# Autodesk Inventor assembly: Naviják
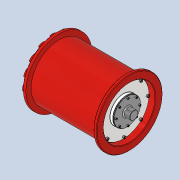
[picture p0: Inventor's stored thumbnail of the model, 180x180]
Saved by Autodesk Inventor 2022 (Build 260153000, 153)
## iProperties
Created: 2025-05
Part Number: Naviják
Document SubType Name: Assembly
Designer: jbart
Author: jbart
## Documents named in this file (37)
- C:\Users\jbart\OneDrive\Dokumenty\Inventor\Převodovka navijáku\Naviják.iam
- C:\Users\jbart\OneDrive\Dokumenty\Inventor\Převodovka navijáku\Bočnice.ipt
- C:\Users\jbart\OneDrive\Dokumenty\Inventor\Převodovka navijáku\Pouzdro.ipt
- C:\Users\jbart\OneDrive\Dokumenty\Inventor\Content Center Files\R2022\cs-CZ\CSN 02 4630\CSN 02 4630 - 6414.ipt
- C:\Users\jbart\OneDrive\Dokumenty\Inventor\Content Center Files\R2022\cs-CZ\CSN 02 2931\CSN 02 2931 - 180.ipt
- C:\Users\jbart\OneDrive\Dokumenty\Inventor\Content Center Files\R2022\cs-CZ\CSN 02 2930\CSN 02 2930 - 70.ipt
- C:\Users\jbart\OneDrive\Dokumenty\Inventor\Převodovka navijáku\Hřídel I.ipt
- C:\Users\jbart\OneDrive\Dokumenty\Inventor\Content Center Files\R2022\cs-CZ\CSN 02 2562  A\CSN 02 2562 - 16x10x50.ipt
- C:\Users\jbart\OneDrive\Dokumenty\Inventor\Převodovka navijáku\Hřídel II.iam
- C:\Users\jbart\OneDrive\Dokumenty\Inventor\Content Center Files\R2022\cs-CZ\CSN 02 2930\CSN 02 2930 - 40.ipt
- C:\Users\jbart\OneDrive\Dokumenty\Inventor\Content Center Files\R2022\cs-CZ\CSN 02 4630\CSN 02 4630 - 6208.ipt
- C:\Users\jbart\OneDrive\Dokumenty\Inventor\Content Center Files\R2022\cs-CZ\CSN 02 4720\CSN  02 4720 - 32948.ipt
- C:\Users\jbart\OneDrive\Dokumenty\Inventor\Content Center Files\R2022\cs-CZ\CSN 02 4720\CSN  02 4720 - 32952.ipt
- C:\Users\jbart\OneDrive\Dokumenty\Inventor\Převodovka navijáku\Unášeč B-2.ipt
- C:\Users\jbart\OneDrive\Dokumenty\Inventor\Převodovka navijáku\Korunové kolo 1.iam
- C:\Users\jbart\OneDrive\Dokumenty\Inventor\Převodovka navijáku\Satelit B.iam
- C:\Users\jbart\OneDrive\Dokumenty\Inventor\Převodovka navijáku\Hřídel V.ipt
- C:\Users\jbart\OneDrive\Dokumenty\Inventor\Content Center Files\R2022\cs-CZ\CSN 02 4630\CSN 02 4630 - 6010.ipt
- C:\Users\jbart\OneDrive\Dokumenty\Inventor\Převodovka navijáku\Distanční kroužek.ipt
- C:\Users\jbart\OneDrive\Dokumenty\Inventor\Content Center Files\R2022\cs-CZ\CSN 02 2930\CSN 02 2930 - 50.ipt
- C:\Users\jbart\OneDrive\Dokumenty\Inventor\Převodovka navijáku\Unášeč B-1.ipt
- C:\Users\jbart\OneDrive\Dokumenty\Inventor\Převodovka navijáku\Unášeč A-2.ipt
- C:\Users\jbart\OneDrive\Dokumenty\Inventor\Převodovka navijáku\Hřídel III.iam
- C:\Users\jbart\OneDrive\Dokumenty\Inventor\Převodovka navijáku\Hřídel IV.ipt
- C:\Users\jbart\OneDrive\Dokumenty\Inventor\Převodovka navijáku\Satelit A.iam
- C:\Users\jbart\OneDrive\Dokumenty\Inventor\Převodovka navijáku\Unášeč A-1.ipt
- C:\Users\jbart\OneDrive\Dokumenty\Inventor\Převodovka navijáku\Korunové kolo 2.iam
- C:\Users\jbart\OneDrive\Dokumenty\Inventor\Převodovka navijáku\Pouzdro II.ipt
- C:\Users\jbart\OneDrive\Dokumenty\Inventor\Content Center Files\R2022\cs-CZ\CSN 02 1143  A\CSN 02 1143 - M12 x 1,75 x 25(1).ipt
- C:\Users\jbart\OneDrive\Dokumenty\Inventor\Převodovka navijáku\Víčko.ipt
- C:\Users\jbart\OneDrive\Dokumenty\Inventor\Content Center Files\R2022\cs-CZ\CSN 02 1143  A\CSN 02 1143 - M12 x 1,75 x 20(1).ipt
- C:\Users\jbart\OneDrive\Dokumenty\Inventor\Převodovka navijáku\Víčko II.ipt
- C:\Users\jbart\OneDrive\Dokumenty\Inventor\Převodovka navijáku\Výstup.ipt
- C:\Users\jbart\OneDrive\Dokumenty\Inventor\Content Center Files\R2022\cs-CZ\CSN 02 1143  A\CSN 02 1143 - M12 x 1,75 x 22(1).ipt
- C:\Users\jbart\OneDrive\Dokumenty\Inventor\Převodovka navijáku\Buben.ipt
- C:\Users\jbart\OneDrive\Dokumenty\Inventor\Content Center Files\R2022\cs-CZ\CSN 02 1143  A\CSN 02 1143 - M16 x 2 x 45(1).ipt
- C:\Users\jbart\OneDrive\Dokumenty\Inventor\Převodovka navijáku\Distanční kroužek II.ipt
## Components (112 placed, 36 different names)
1. Bočnice:1 — Stejný směr:1, Proti sobě:1, Proti sobě:2, Proti sobě:5, Proti sobě:6, Stejný směr:2, Stejný směr:3, Proti sobě:23, Proti sobě:24, Proti sobě:25, Stejný směr:4, Proti sobě:27, Proti sobě:28, Proti sobě:29, Proti sobě:30, Proti sobě:31, Proti sobě:32, Proti sobě:35, Proti sobě:145, Proti sobě:146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
2. Pouzdro:1 — Proti sobě:7, Proti sobě:8, Proti sobě:9, Proti sobě:10, Proti sobě:14, Proti sobě:15, Proti sobě:16, Proti sobě:17, Proti sobě:18
3. CSN 02 4630 6414:1 — Proti sobě:143, Proti sobě:144
4. CSN 02 4630 6414:2 — Proti sobě:7, Proti sobě:10, Proti sobě:27, Proti sobě:28
5. CSN 02 2931 180:1 — Proti sobě:5, Proti sobě:6, Stejný směr:2
6. CSN 02 2930 70:1 — Proti sobě:8, Proti sobě:9, Stejný směr:3
7. Hřídel I:1 — Proti sobě:11, Proti sobě:12, Proti sobě:13, Proti sobě:14, Proti sobě:150
8. CSN 02 2562 A 16x10x50:1 — Proti sobě:11, Proti sobě:12, Proti sobě:13, Proti sobě:15
9. Hřídel II:1 [sub-assembly] — Proti sobě:16, Proti sobě:17, Proti sobě:18, Proti sobě:19, Proti sobě:20, Proti sobě:21, Proti sobě:22, Proti sobě:26, Proti sobě:34, Proti sobě:52, Rotace:4, Rotace:5, Rotace:6, Rotace:7, Proti sobě:138, Proti sobě:167
10. CSN 02 2930 40:1 — Proti sobě:21, Proti sobě:22
11. CSN 02 4630 6208:1 — Proti sobě:19, Proti sobě:20, Proti sobě:151, Proti sobě:152
12. CSN 02 4720 32948:1 — Proti sobě:23, Proti sobě:24, Proti sobě:142
13. CSN 02 4720 32952:1 — Proti sobě:25, Stejný směr:4, Stejný směr:10
14. Unášeč B-2:1 — Proti sobě:26, Proti sobě:29, Proti sobě:30, Proti sobě:31, Proti sobě:33, Proti sobě:49, Proti sobě:50, Proti sobě:51, Proti sobě:68, Proti sobě:69, Proti sobě:70, Proti sobě:84, Proti sobě:85, Proti sobě:86
15. Korunové kolo 1:1 [sub-assembly] — Proti sobě:34, Proti sobě:35, Stejný směr:8, Proti sobě:141
16. Satelit B:1 [sub-assembly] — Proti sobě:36, Proti sobě:37, Proti sobě:38, Proti sobě:39, Rotace:1, Stejný směr:7
17. Hřídel V:1 — Proti sobě:40, Proti sobě:41, Proti sobě:43, Proti sobě:45, Proti sobě:46, Proti sobě:47, Proti sobě:48, Proti sobě:49, Proti sobě:53
18. CSN 02 4630 6010:1 — Proti sobě:36, Proti sobě:37, Proti sobě:40, Proti sobě:42
19. CSN 02 4630 6010:2 — Proti sobě:38, Proti sobě:39, Proti sobě:44
20. Distanční kroužek:1 — Proti sobě:41, Proti sobě:42, Proti sobě:51
21. Distanční kroužek:2 — Proti sobě:43, Proti sobě:44, Proti sobě:54
22. CSN 02 2930 50:1 — Proti sobě:45, Proti sobě:48, Proti sobě:50
23. CSN 02 2930 50:2 — Proti sobě:46, Proti sobě:47
24. Unášeč B-1:1 — Proti sobě:52, Proti sobě:53, Proti sobě:54, Proti sobě:87
25. Satelit B:2 [sub-assembly] — Rotace:3, Stejný směr:9
26. Hřídel V:2 — Proti sobě:68
27. CSN 02 4630 6010:3
28. CSN 02 4630 6010:4
29. Distanční kroužek:3 — Proti sobě:70
30. Distanční kroužek:4
31. CSN 02 2930 50:3 — Proti sobě:69
32. CSN 02 2930 50:4
33. Satelit B:3 [sub-assembly] — Rotace:2
34. Hřídel V:3 — Proti sobě:84
35. CSN 02 4630 6010:5
36. CSN 02 4630 6010:6
37. Distanční kroužek:5 — Proti sobě:86
38. Distanční kroužek:6
39. CSN 02 2930 50:5 — Proti sobě:85
40. CSN 02 2930 50:6
41. Unášeč A-2:1 — Proti sobě:87, Proti sobě:88, Proti sobě:89, Stejný směr:6, Proti sobě:103, Proti sobě:104, Proti sobě:105, Proti sobě:132, Proti sobě:133, Proti sobě:134, Proti sobě:135, Proti sobě:136, Proti sobě:137, Rotace:7
42. Hřídel III:1 [sub-assembly] — Proti sobě:88, Proti sobě:89, Stejný směr:6, Rotace:1, Rotace:2, Rotace:3, Stejný směr:7, Rotace:8, Proti sobě:168
43. Hřídel IV:1 — Proti sobě:94, Proti sobě:95, Proti sobě:97, Proti sobě:99, Proti sobě:100, Proti sobě:101, Proti sobě:102, Proti sobě:103, Proti sobě:139
44. Distanční kroužek:7 — Proti sobě:95, Proti sobě:96, Proti sobě:105
45. Distanční kroužek:8 — Proti sobě:97, Proti sobě:98, Proti sobě:140
46. CSN 02 2930 50:7 — Proti sobě:101, Proti sobě:102
47. CSN 02 2930 50:8 — Proti sobě:99, Proti sobě:100, Proti sobě:104
48. Satelit A:1 [sub-assembly] — Proti sobě:90, Proti sobě:91, Proti sobě:92, Proti sobě:93, Rotace:5, Stejný směr:8
49. CSN 02 4630 6010:7 — Proti sobě:90, Proti sobě:91, Proti sobě:94, Proti sobě:96
50. CSN 02 4630 6010:8 — Proti sobě:92, Proti sobě:93, Proti sobě:98
51. Hřídel IV:2 — Proti sobě:135
52. Distanční kroužek:9 — Proti sobě:137
53. Distanční kroužek:10
54. CSN 02 2930 50:9
55. CSN 02 2930 50:10 — Proti sobě:136
56. Satelit A:2 [sub-assembly] — Rotace:4
57. CSN 02 4630 6010:9
58. CSN 02 4630 6010:10
59. Hřídel IV:3 — Proti sobě:132
60. Distanční kroužek:11 — Proti sobě:134
61. Distanční kroužek:12
62. CSN 02 2930 50:11
63. CSN 02 2930 50:12 — Proti sobě:133
64. Satelit A:3 [sub-assembly] — Rotace:6
65. CSN 02 4630 6010:11
66. CSN 02 4630 6010:12
67. Unášeč A-1:1 — Proti sobě:138, Proti sobě:139, Proti sobě:140
68. Korunové kolo 2:1 [sub-assembly] — Proti sobě:141, Stejný směr:9, Rotace:8, Proti sobě:158, Proti sobě:159
69. Pouzdro II:1 — Proti sobě:142, Stejný směr:10, Proti sobě:160, Proti sobě:161, Proti sobě:163, Stejný směr:11
70. Víčko:1 — Proti sobě:143, Proti sobě:144, Proti sobě:145, Proti sobě:146, Proti sobě:147, Proti sobě:149, Proti sobě:150
71. Víčko II:1 — Proti sobě:151, Proti sobě:152, Proti sobě:153, Proti sobě:154, Proti sobě:155, Proti sobě:164, Proti sobě:165, Proti sobě:166
72. Výstup:1 — Proti sobě:153, Proti sobě:154, Proti sobě:155, Proti sobě:156, Proti sobě:157
73. Buben:1 — Proti sobě:158, Proti sobě:159, Proti sobě:160, Proti sobě:164
74. Distanční kroužek II:1 — Proti sobě:167, Proti sobě:168
75. CSN 02 1143 A M12 x 25:1 — Proti sobě:32, Proti sobě:33
76. CSN 02 1143 A M12 x 25:2
77. CSN 02 1143 A M12 x 25:3
78. CSN 02 1143 A M12 x 25:4
79. CSN 02 1143 A M12 x 25:5
80. CSN 02 1143 A M12 x 25:6
81. CSN 02 1143 A M12 x 20:1 — Proti sobě:148, Proti sobě:149
82. CSN 02 1143 A M12 x 20:2
83. CSN 02 1143 A M12 x 20:3
84. CSN 02 1143 A M12 x 20:4
85. CSN 02 1143 A M12 x 20:5
86. CSN 02 1143 A M12 x 20:6
87. CSN 02 1143 A M12 x 20:7
88. CSN 02 1143 A M12 x 20:8
89. CSN 02 1143 A M12 x 22:1 — Proti sobě:156, Proti sobě:157
90. CSN 02 1143 A M12 x 22:2
91. CSN 02 1143 A M12 x 22:3
92. CSN 02 1143 A M12 x 22:4
93. CSN 02 1143 A M12 x 22:5
94. CSN 02 1143 A M12 x 22:6
95. CSN 02 1143 A M12 x 22:7
96. CSN 02 1143 A M12 x 22:8
97. CSN 02 1143 A M16 x 45:1 — Proti sobě:161, Proti sobě:163
98. CSN 02 1143 A M16 x 45:3
99. CSN 02 1143 A M16 x 45:4
100. CSN 02 1143 A M16 x 45:5
101. CSN 02 1143 A M16 x 45:6
102. CSN 02 1143 A M16 x 45:7
103. CSN 02 1143 A M16 x 45:8
104. CSN 02 1143 A M16 x 45:9
105. CSN 02 1143 A M16 x 45:2 — Proti sobě:165, Proti sobě:166
106. CSN 02 1143 A M16 x 45:10
107. CSN 02 1143 A M16 x 45:11
108. CSN 02 1143 A M16 x 45:12
109. CSN 02 1143 A M16 x 45:13
110. CSN 02 1143 A M16 x 45:14
111. CSN 02 1143 A M16 x 45:15
112. CSN 02 1143 A M16 x 45:16
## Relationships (131: Mate 113, Flush 10, RelateRotation 8)
- Stejný směr:1 [Flush]: Bočnice:1
- Proti sobě:1 [Mate]: Bočnice:1
- Proti sobě:2 [Mate]: Bočnice:1
- Proti sobě:5 [Mate]: Bočnice:1 ↔ CSN 02 2931 180:1
- Proti sobě:6 [Mate]: Bočnice:1 ↔ CSN 02 2931 180:1
- Stejný směr:2 [Flush]: Bočnice:1 ↔ CSN 02 2931 180:1
- Proti sobě:7 [Mate]: Pouzdro:1 ↔ CSN 02 4630 6414:2
- Proti sobě:8 [Mate]: Pouzdro:1 ↔ CSN 02 2930 70:1
- Proti sobě:9 [Mate]: Pouzdro:1 ↔ CSN 02 2930 70:1
- Stejný směr:3 [Flush]: Bočnice:1 ↔ CSN 02 2930 70:1
- Proti sobě:10 [Mate]: Pouzdro:1 ↔ CSN 02 4630 6414:2
- Proti sobě:11 [Mate]: Hřídel I:1 ↔ CSN 02 2562 A 16x10x50:1
- Proti sobě:12 [Mate]: Hřídel I:1 ↔ CSN 02 2562 A 16x10x50:1
- Proti sobě:13 [Mate]: Hřídel I:1 ↔ CSN 02 2562 A 16x10x50:1
- Proti sobě:14 [Mate]: Pouzdro:1 ↔ Hřídel I:1
- Proti sobě:15 [Mate]: Pouzdro:1 ↔ CSN 02 2562 A 16x10x50:1
- Proti sobě:16 [Mate]: Pouzdro:1 ↔ Hřídel II:1
- Proti sobě:17 [Mate]: Pouzdro:1 ↔ Hřídel II:1
- Proti sobě:18 [Mate]: Pouzdro:1 ↔ Hřídel II:1
- Proti sobě:19 [Mate]: Hřídel II:1 ↔ CSN 02 4630 6208:1
- Proti sobě:20 [Mate]: Hřídel II:1 ↔ CSN 02 4630 6208:1
- Proti sobě:21 [Mate]: Hřídel II:1 ↔ CSN 02 2930 40:1
- Proti sobě:22 [Mate]: Hřídel II:1 ↔ CSN 02 2930 40:1
- Proti sobě:23 [Mate]: Bočnice:1 ↔ CSN 02 4720 32948:1
- Proti sobě:24 [Mate]: Bočnice:1 ↔ CSN 02 4720 32948:1
- Proti sobě:25 [Mate]: Bočnice:1 ↔ CSN 02 4720 32952:1
- Stejný směr:4 [Flush]: Bočnice:1 ↔ CSN 02 4720 32952:1
- Proti sobě:26 [Mate]: Hřídel II:1 ↔ Unášeč B-2:1
- Proti sobě:27 [Mate]: Bočnice:1 ↔ CSN 02 4630 6414:2
- Proti sobě:28 [Mate]: Bočnice:1 ↔ CSN 02 4630 6414:2
- Proti sobě:29 [Mate]: Bočnice:1 ↔ Unášeč B-2:1
- Proti sobě:30 [Mate]: Bočnice:1 ↔ Unášeč B-2:1
- Proti sobě:31 [Mate]: Bočnice:1 ↔ Unášeč B-2:1
- Proti sobě:32 [Mate]: Bočnice:1 ↔ CSN 02 1143 A M12 x 25:1
- Proti sobě:33 [Mate]: Unášeč B-2:1 ↔ CSN 02 1143 A M12 x 25:1
- Proti sobě:34 [Mate]: Hřídel II:1 ↔ Korunové kolo 1:1
- Proti sobě:35 [Mate]: Bočnice:1 ↔ Korunové kolo 1:1
- Proti sobě:36 [Mate]: Satelit B:1 ↔ CSN 02 4630 6010:1
- Proti sobě:37 [Mate]: Satelit B:1 ↔ CSN 02 4630 6010:1
- Proti sobě:38 [Mate]: Satelit B:1 ↔ CSN 02 4630 6010:2
- Proti sobě:39 [Mate]: Satelit B:1 ↔ CSN 02 4630 6010:2
- Proti sobě:40 [Mate]: Hřídel V:1 ↔ CSN 02 4630 6010:1
- Proti sobě:41 [Mate]: Hřídel V:1 ↔ Distanční kroužek:1
- Proti sobě:42 [Mate]: CSN 02 4630 6010:1 ↔ Distanční kroužek:1
- Proti sobě:43 [Mate]: Hřídel V:1 ↔ Distanční kroužek:2
- Proti sobě:44 [Mate]: CSN 02 4630 6010:2 ↔ Distanční kroužek:2
- Proti sobě:45 [Mate]: Hřídel V:1 ↔ CSN 02 2930 50:1
- Proti sobě:46 [Mate]: Hřídel V:1 ↔ CSN 02 2930 50:2
- Proti sobě:47 [Mate]: Hřídel V:1 ↔ CSN 02 2930 50:2
- Proti sobě:48 [Mate]: Hřídel V:1 ↔ CSN 02 2930 50:1
- Proti sobě:49 [Mate]: Unášeč B-2:1 ↔ Hřídel V:1
- Proti sobě:50 [Mate]: Unášeč B-2:1 ↔ CSN 02 2930 50:1
- Proti sobě:51 [Mate]: Unášeč B-2:1 ↔ Distanční kroužek:1
- Proti sobě:52 [Mate]: Hřídel II:1 ↔ Unášeč B-1:1
- Proti sobě:53 [Mate]: Hřídel V:1 ↔ Unášeč B-1:1
- Proti sobě:54 [Mate]: Distanční kroužek:2 ↔ Unášeč B-1:1
- Proti sobě:68 [Mate]: Unášeč B-2:1 ↔ Hřídel V:2
- Proti sobě:69 [Mate]: Unášeč B-2:1 ↔ CSN 02 2930 50:3
- Proti sobě:70 [Mate]: Unášeč B-2:1 ↔ Distanční kroužek:3
- Proti sobě:84 [Mate]: Unášeč B-2:1 ↔ Hřídel V:3
- Proti sobě:85 [Mate]: Unášeč B-2:1 ↔ CSN 02 2930 50:5
- Proti sobě:86 [Mate]: Unášeč B-2:1 ↔ Distanční kroužek:5
- Proti sobě:87 [Mate]: Unášeč B-1:1 ↔ Unášeč A-2:1
- Proti sobě:88 [Mate]: Unášeč A-2:1 ↔ Hřídel III:1
- Proti sobě:89 [Mate]: Unášeč A-2:1 ↔ Hřídel III:1
- Stejný směr:6 [Flush]: Unášeč A-2:1 ↔ Hřídel III:1
- Rotace:1 [RelateRotation]: Satelit B:1 ↔ Hřídel III:1
- Rotace:2 [RelateRotation]: Satelit B:3 ↔ Hřídel III:1
- Rotace:3 [RelateRotation]: Satelit B:2 ↔ Hřídel III:1
- Stejný směr:7 [Flush]: Satelit B:1 ↔ Hřídel III:1
- Proti sobě:90 [Mate]: Satelit A:1 ↔ CSN 02 4630 6010:7
- Proti sobě:91 [Mate]: Satelit A:1 ↔ CSN 02 4630 6010:7
- Proti sobě:92 [Mate]: Satelit A:1 ↔ CSN 02 4630 6010:8
- Proti sobě:93 [Mate]: Satelit A:1 ↔ CSN 02 4630 6010:8
- Proti sobě:94 [Mate]: Hřídel IV:1 ↔ CSN 02 4630 6010:7
- Proti sobě:95 [Mate]: Hřídel IV:1 ↔ Distanční kroužek:7
- Proti sobě:96 [Mate]: Distanční kroužek:7 ↔ CSN 02 4630 6010:7
- Proti sobě:97 [Mate]: Hřídel IV:1 ↔ Distanční kroužek:8
- Proti sobě:98 [Mate]: Distanční kroužek:8 ↔ CSN 02 4630 6010:8
- Proti sobě:99 [Mate]: Hřídel IV:1 ↔ CSN 02 2930 50:8
- Proti sobě:100 [Mate]: Hřídel IV:1 ↔ CSN 02 2930 50:8
- Proti sobě:101 [Mate]: Hřídel IV:1 ↔ CSN 02 2930 50:7
- Proti sobě:102 [Mate]: Hřídel IV:1 ↔ CSN 02 2930 50:7
- Proti sobě:103 [Mate]: Unášeč A-2:1 ↔ Hřídel IV:1
- Proti sobě:104 [Mate]: Unášeč A-2:1 ↔ CSN 02 2930 50:8
- Proti sobě:105 [Mate]: Unášeč A-2:1 ↔ Distanční kroužek:7
- Proti sobě:132 [Mate]: Unášeč A-2:1 ↔ Hřídel IV:3
- Proti sobě:133 [Mate]: Unášeč A-2:1 ↔ CSN 02 2930 50:12
- Proti sobě:134 [Mate]: Unášeč A-2:1 ↔ Distanční kroužek:11
- Proti sobě:135 [Mate]: Unášeč A-2:1 ↔ Hřídel IV:2
- Proti sobě:136 [Mate]: Unášeč A-2:1 ↔ CSN 02 2930 50:10
- Proti sobě:137 [Mate]: Unášeč A-2:1 ↔ Distanční kroužek:9
- Rotace:4 [RelateRotation]: Hřídel II:1 ↔ Satelit A:2
- Rotace:5 [RelateRotation]: Hřídel II:1 ↔ Satelit A:1
- Rotace:6 [RelateRotation]: Hřídel II:1 ↔ Satelit A:3
- Rotace:7 [RelateRotation]: Hřídel II:1 ↔ Unášeč A-2:1
- Stejný směr:8 [Flush]: Korunové kolo 1:1 ↔ Satelit A:1
- Proti sobě:138 [Mate]: Hřídel II:1 ↔ Unášeč A-1:1
- Proti sobě:139 [Mate]: Hřídel IV:1 ↔ Unášeč A-1:1
- Proti sobě:140 [Mate]: Distanční kroužek:8 ↔ Unášeč A-1:1
- Proti sobě:141 [Mate]: Korunové kolo 1:1 ↔ Korunové kolo 2:1
- Stejný směr:9 [Flush]: Satelit B:2 ↔ Korunové kolo 2:1
- Rotace:8 [RelateRotation]: Hřídel III:1 ↔ Korunové kolo 2:1
- Proti sobě:142 [Mate]: CSN 02 4720 32948:1 ↔ Pouzdro II:1
- Stejný směr:10 [Flush]: CSN 02 4720 32952:1 ↔ Pouzdro II:1
- Proti sobě:143 [Mate]: CSN 02 4630 6414:1 ↔ Víčko:1
- Proti sobě:144 [Mate]: CSN 02 4630 6414:1 ↔ Víčko:1
- Proti sobě:145 [Mate]: Bočnice:1 ↔ Víčko:1
- Proti sobě:146 [Mate]: Bočnice:1 ↔ Víčko:1
- Proti sobě:147 [Mate]: Bočnice:1 ↔ Víčko:1
- Proti sobě:148 [Mate]: Bočnice:1 ↔ CSN 02 1143 A M12 x 20:1
- Proti sobě:149 [Mate]: Víčko:1 ↔ CSN 02 1143 A M12 x 20:1
- Proti sobě:150 [Mate]: Hřídel I:1 ↔ Víčko:1
- Proti sobě:151 [Mate]: CSN 02 4630 6208:1 ↔ Víčko II:1
- Proti sobě:152 [Mate]: CSN 02 4630 6208:1 ↔ Víčko II:1
- Proti sobě:153 [Mate]: Víčko II:1 ↔ Výstup:1
- Proti sobě:154 [Mate]: Víčko II:1 ↔ Výstup:1
- Proti sobě:155 [Mate]: Víčko II:1 ↔ Výstup:1
- Proti sobě:156 [Mate]: Výstup:1 ↔ CSN 02 1143 A M12 x 22:1
- Proti sobě:157 [Mate]: Výstup:1 ↔ CSN 02 1143 A M12 x 22:1
- Proti sobě:158 [Mate]: Korunové kolo 2:1 ↔ Buben:1
- Proti sobě:159 [Mate]: Korunové kolo 2:1 ↔ Buben:1
- Proti sobě:160 [Mate]: Pouzdro II:1 ↔ Buben:1
- Proti sobě:161 [Mate]: Pouzdro II:1 ↔ CSN 02 1143 A M16 x 45:1
- Proti sobě:163 [Mate]: Pouzdro II:1 ↔ CSN 02 1143 A M16 x 45:1
- Proti sobě:164 [Mate]: Víčko II:1 ↔ Buben:1
- Proti sobě:165 [Mate]: Víčko II:1 ↔ CSN 02 1143 A M16 x 45:2
- Proti sobě:166 [Mate]: Víčko II:1 ↔ CSN 02 1143 A M16 x 45:2
- Stejný směr:11 [Flush]: Pouzdro II:1
- Proti sobě:167 [Mate]: Hřídel II:1 ↔ Distanční kroužek II:1
- Proti sobě:168 [Mate]: Hřídel III:1 ↔ Distanční kroužek II:1
## Named parameters: d66_d56 = 0, d67_d57 = 0, d68_d58 = 0, d69_d46 = 0, d70_d47 = 0, d71_d48 = 0, d72_d49 = 0, d73_d50 = 0, d74_d51 = 0, d75_d52 = 0, d76_d53 = 0, d77_d54 = 0, d78_d55 = 0, d82_d56 = 0, d83_d57 = 0, d84_d58 = 0, d85_d46 = 0, d86_d47 = 0, d87_d48 = 0, d88_d49 = 0, d89_d50 = 0, d90_d51 = 0, d91_d52 = 0, d92_d53 = 0, d93_d54 = 0, d94_d55 = 0, d123_d107 = 0, d124_d108 = 0, d125_d109 = 0, d126_d110 = 0, d127_d111 = 0, d128_d112 = 0, d129_d113 = 0, d130_d114 = 0, d131_d115 = 0, d132_d116 = 0, d133_d117 = 0, d134_d118 = 0, d135_d119 = 0, d136_d107 = 0, d137_d108 = 0, d138_d109 = 0, d139_d110 = 0, d140_d111 = 0, d141_d112 = 0, d142_d113 = 0, d143_d114 = 0, d144_d115 = 0, d145_d116 = 0, d146_d117 = 0, d147_d118 = 0, d148_d119 = 0
